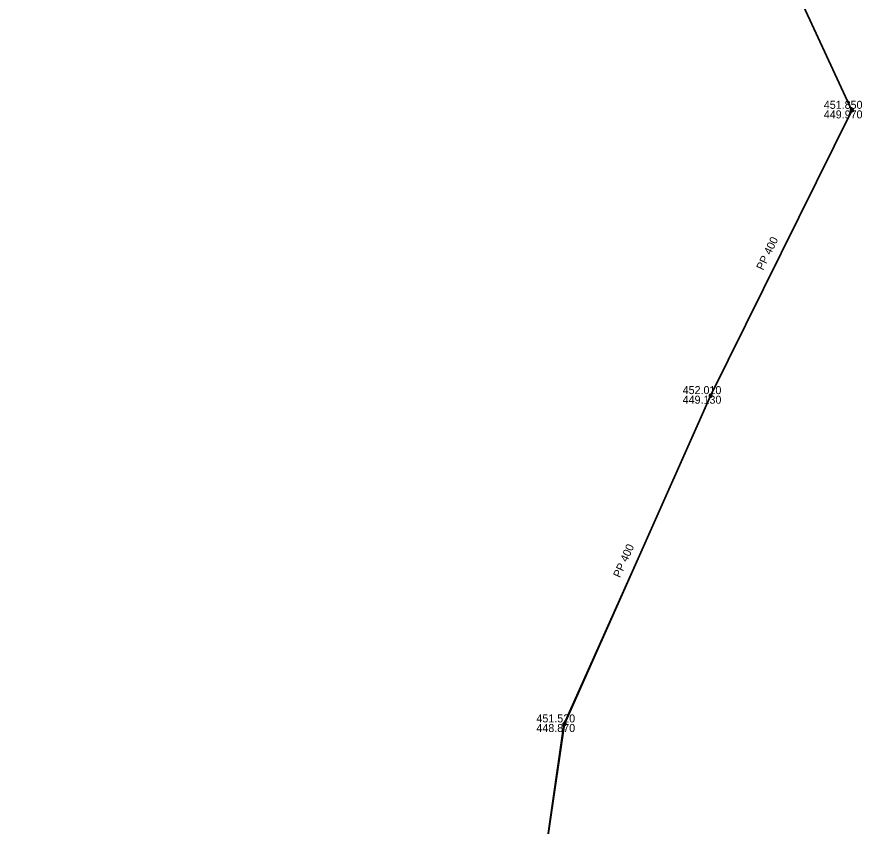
# Model space of a CAD drawing. Extents: x -873619 to -867639, y -1015082 to -1012326.
# Drawn here: x -873191.6 to -873075.5, y -1013871.2 to -1013760 of the extents above; entities that cross this region are included whole.
import ezdxf

# ---------------------------------------------------------------- set-up
doc = ezdxf.new("R2010")
doc.units = 0
doc.header["$LTSCALE"] = 0.44
for name, color, linetype, lineweight in [('1', 7, 'Continuous', 13), ('21', 7, 'Continuous', 35), ('3', 7, 'Continuous', 25), ('32', 7, 'Continuous', 13)]:
    doc.layers.add(name, color=color, linetype=linetype, lineweight=lineweight)

msp = doc.modelspace()

# ---------------------------------------------------------------- linework, layer by layer
at = {"layer": '21'}
for p, q in [((-873099.19, -1013724.68), (-873076.92, -1013772.84)), ((-873076.92, -1013772.84), (-873096.31, -1013812.05)), ((-873096.31, -1013812.05), (-873116.4, -1013857.17)), ((-873116.4, -1013857.17), (-873123.67, -1013906.71))]:
    msp.add_line(p, q, dxfattribs=at)
at = {"layer": '3'}
msp.add_lwpolyline([(-873209.421, -1014292.661), (-873208.998, -1014240.45), (-873211.448, -1014197.31), (-873215.58, -1014166.03), (-873205.44, -1014160.07), (-873195.92, -1014151.84), (-873190.998, -1014149.15), (-873189.02, -1014105.45), (-873184.64, -1014067), (-873178.998, -1014022.35), (-873173.208, -1014002.85), (-873150.578, -1013958.19), (-873123.56, -1013906.71), (-873116.49, -1013857.17), (-873096.298, -1013812.05), (-873076.908, -1013772.84), (-873099.08, -1013724.68), (-873112.568, -1013694.19), (-873154.458, -1013666.63), (-873180.788, -1013644.59), (-873224.641, -1013607.538), (-873251.958, -1013559.37), (-873281.448, -1013506.61), (-873307.717, -1013457.772)], dxfattribs=at)
at = {"layer": '32'}
for points in [[(-873076.679, -1013772.84), (-873076.685, -1013772.788), (-873076.702, -1013772.738), (-873076.731, -1013772.694), (-873076.768, -1013772.657), (-873076.813, -1013772.63), (-873076.863, -1013772.613), (-873076.916, -1013772.609), (-873076.968, -1013772.616), (-873077.017, -1013772.635), (-873077.06, -1013772.664), (-873077.096, -1013772.703), (-873077.122, -1013772.748), (-873077.138, -1013772.799), (-873077.141, -1013772.851), (-873077.133, -1013772.903), (-873077.113, -1013772.952), (-873077.082, -1013772.995), (-873077.043, -1013773.029), (-873076.997, -1013773.055), (-873076.946, -1013773.069), (-873076.893, -1013773.071), (-873076.842, -1013773.061), (-873076.794, -1013773.04), (-873076.751, -1013773.009), (-873076.717, -1013772.968), (-873076.693, -1013772.922), (-873076.681, -1013772.871)], [(-873076.709, -1013772.84), (-873076.715, -1013772.791), (-873076.732, -1013772.745), (-873076.76, -1013772.705), (-873076.797, -1013772.673), (-873076.841, -1013772.651), (-873076.889, -1013772.64), (-873076.938, -1013772.64), (-873076.985, -1013772.653), (-873077.028, -1013772.677), (-873077.064, -1013772.71), (-873077.091, -1013772.751), (-873077.107, -1013772.798), (-873077.111, -1013772.847), (-873077.104, -1013772.895), (-873077.085, -1013772.94), (-873077.055, -1013772.98), (-873077.017, -1013773.011), (-873076.973, -1013773.031), (-873076.925, -1013773.041), (-873076.876, -1013773.039), (-873076.829, -1013773.024), (-873076.786, -1013772.999), (-873076.752, -1013772.965), (-873076.726, -1013772.923), (-873076.712, -1013772.876)], [(-873076.739, -1013772.84), (-873076.745, -1013772.795), (-873076.762, -1013772.753), (-873076.79, -1013772.718), (-873076.826, -1013772.691), (-873076.868, -1013772.674), (-873076.913, -1013772.669), (-873076.958, -1013772.675), (-873076.999, -1013772.694), (-873077.034, -1013772.722), (-873077.061, -1013772.759), (-873077.077, -1013772.801), (-873077.081, -1013772.846), (-873077.074, -1013772.891), (-873077.055, -1013772.932), (-873077.026, -1013772.966), (-873076.989, -1013772.992), (-873076.946, -1013773.008), (-873076.901, -1013773.011), (-873076.856, -1013773.003), (-873076.816, -1013772.983), (-873076.782, -1013772.954), (-873076.756, -1013772.916), (-873076.742, -1013772.873)], [(-873076.769, -1013772.84), (-873076.774, -1013772.799), (-873076.792, -1013772.762), (-873076.819, -1013772.731), (-873076.854, -1013772.71), (-873076.894, -1013772.699), (-873076.935, -1013772.701), (-873076.974, -1013772.714), (-873077.008, -1013772.738), (-873077.033, -1013772.77), (-873077.048, -1013772.808), (-873077.051, -1013772.849), (-873077.043, -1013772.889), (-873077.023, -1013772.925), (-873076.994, -1013772.954), (-873076.957, -1013772.973), (-873076.917, -1013772.981), (-873076.876, -1013772.977), (-873076.838, -1013772.962), (-873076.806, -1013772.936), (-873076.783, -1013772.902), (-873076.77, -1013772.863)], [(-873076.799, -1013772.84), (-873076.804, -1013772.804), (-873076.822, -1013772.772), (-873076.848, -1013772.747), (-873076.882, -1013772.732), (-873076.918, -1013772.729), (-873076.953, -1013772.737), (-873076.984, -1013772.757), (-873077.007, -1013772.785), (-873077.02, -1013772.819), (-873077.02, -1013772.856), (-873077.009, -1013772.891), (-873076.988, -1013772.92), (-873076.958, -1013772.941), (-873076.923, -1013772.951), (-873076.886, -1013772.949), (-873076.852, -1013772.935), (-873076.825, -1013772.912), (-873076.806, -1013772.88), (-873076.799, -1013772.845)], [(-873076.829, -1013772.84), (-873076.834, -1013772.809), (-873076.851, -1013772.783), (-873076.877, -1013772.766), (-873076.907, -1013772.759), (-873076.938, -1013772.763), (-873076.965, -1013772.78), (-873076.983, -1013772.804), (-873076.991, -1013772.835), (-873076.987, -1013772.865), (-873076.972, -1013772.893), (-873076.948, -1013772.912), (-873076.918, -1013772.921), (-873076.887, -1013772.918), (-873076.859, -1013772.904), (-873076.839, -1013772.88), (-873076.829, -1013772.851)], [(-873076.859, -1013772.84), (-873076.864, -1013772.816), (-873076.881, -1013772.798), (-873076.904, -1013772.789), (-873076.928, -1013772.792), (-873076.949, -1013772.806), (-873076.96, -1013772.828), (-873076.96, -1013772.853), (-873076.948, -1013772.874), (-873076.928, -1013772.888), (-873076.903, -1013772.891), (-873076.88, -1013772.882), (-873076.864, -1013772.864)], [(-873076.889, -1013772.84), (-873076.894, -1013772.825), (-873076.909, -1013772.819), (-873076.924, -1013772.823), (-873076.931, -1013772.837), (-873076.927, -1013772.852), (-873076.914, -1013772.861), (-873076.899, -1013772.858), (-873076.889, -1013772.846)], [(-873096.069, -1013812.05), (-873096.075, -1013811.998), (-873096.092, -1013811.948), (-873096.121, -1013811.904), (-873096.158, -1013811.867), (-873096.203, -1013811.84), (-873096.253, -1013811.823), (-873096.306, -1013811.819), (-873096.358, -1013811.826), (-873096.407, -1013811.845), (-873096.45, -1013811.874), (-873096.486, -1013811.913), (-873096.512, -1013811.958), (-873096.528, -1013812.009), (-873096.531, -1013812.061), (-873096.523, -1013812.113), (-873096.503, -1013812.162), (-873096.472, -1013812.205), (-873096.433, -1013812.239), (-873096.387, -1013812.265), (-873096.336, -1013812.279), (-873096.283, -1013812.281), (-873096.232, -1013812.271), (-873096.184, -1013812.25), (-873096.141, -1013812.219), (-873096.107, -1013812.178), (-873096.083, -1013812.132), (-873096.071, -1013812.081)], [(-873096.099, -1013812.05), (-873096.105, -1013812.001), (-873096.122, -1013811.955), (-873096.15, -1013811.915), (-873096.187, -1013811.883), (-873096.231, -1013811.861), (-873096.279, -1013811.85), (-873096.328, -1013811.85), (-873096.375, -1013811.863), (-873096.418, -1013811.887), (-873096.454, -1013811.92), (-873096.481, -1013811.961), (-873096.497, -1013812.008), (-873096.501, -1013812.057), (-873096.494, -1013812.105), (-873096.475, -1013812.15), (-873096.445, -1013812.19), (-873096.407, -1013812.221), (-873096.363, -1013812.241), (-873096.315, -1013812.251), (-873096.266, -1013812.249), (-873096.219, -1013812.234), (-873096.176, -1013812.209), (-873096.142, -1013812.175), (-873096.116, -1013812.133), (-873096.102, -1013812.086)], [(-873096.129, -1013812.05), (-873096.135, -1013812.005), (-873096.152, -1013811.963), (-873096.18, -1013811.928), (-873096.216, -1013811.901), (-873096.258, -1013811.884), (-873096.303, -1013811.879), (-873096.348, -1013811.885), (-873096.389, -1013811.904), (-873096.424, -1013811.932), (-873096.451, -1013811.969), (-873096.467, -1013812.011), (-873096.471, -1013812.056), (-873096.464, -1013812.101), (-873096.445, -1013812.142), (-873096.416, -1013812.176), (-873096.379, -1013812.202), (-873096.336, -1013812.218), (-873096.291, -1013812.221), (-873096.246, -1013812.213), (-873096.206, -1013812.193), (-873096.172, -1013812.164), (-873096.146, -1013812.126), (-873096.132, -1013812.083)], [(-873096.159, -1013812.05), (-873096.164, -1013812.009), (-873096.182, -1013811.972), (-873096.209, -1013811.941), (-873096.244, -1013811.92), (-873096.284, -1013811.909), (-873096.325, -1013811.911), (-873096.364, -1013811.924), (-873096.398, -1013811.948), (-873096.423, -1013811.98), (-873096.438, -1013812.018), (-873096.441, -1013812.059), (-873096.433, -1013812.099), (-873096.413, -1013812.135), (-873096.384, -1013812.164), (-873096.347, -1013812.183), (-873096.307, -1013812.191), (-873096.266, -1013812.187), (-873096.228, -1013812.172), (-873096.196, -1013812.146), (-873096.173, -1013812.112), (-873096.16, -1013812.073)], [(-873096.189, -1013812.05), (-873096.194, -1013812.014), (-873096.212, -1013811.982), (-873096.238, -1013811.957), (-873096.272, -1013811.942), (-873096.308, -1013811.939), (-873096.343, -1013811.947), (-873096.374, -1013811.967), (-873096.397, -1013811.995), (-873096.41, -1013812.029), (-873096.41, -1013812.066), (-873096.399, -1013812.101), (-873096.378, -1013812.13), (-873096.348, -1013812.151), (-873096.313, -1013812.161), (-873096.276, -1013812.159), (-873096.242, -1013812.145), (-873096.215, -1013812.122), (-873096.196, -1013812.09), (-873096.189, -1013812.055)], [(-873096.219, -1013812.05), (-873096.224, -1013812.019), (-873096.241, -1013811.993), (-873096.267, -1013811.976), (-873096.297, -1013811.969), (-873096.328, -1013811.973), (-873096.355, -1013811.99), (-873096.373, -1013812.014), (-873096.381, -1013812.045), (-873096.377, -1013812.075), (-873096.362, -1013812.103), (-873096.338, -1013812.122), (-873096.308, -1013812.131), (-873096.277, -1013812.128), (-873096.249, -1013812.114), (-873096.229, -1013812.09), (-873096.219, -1013812.061)], [(-873096.249, -1013812.05), (-873096.254, -1013812.026), (-873096.271, -1013812.008), (-873096.294, -1013811.999), (-873096.318, -1013812.002), (-873096.339, -1013812.016), (-873096.35, -1013812.038), (-873096.35, -1013812.063), (-873096.338, -1013812.084), (-873096.318, -1013812.098), (-873096.293, -1013812.101), (-873096.27, -1013812.092), (-873096.254, -1013812.074)], [(-873096.279, -1013812.05), (-873096.284, -1013812.035), (-873096.299, -1013812.029), (-873096.314, -1013812.033), (-873096.321, -1013812.047), (-873096.317, -1013812.062), (-873096.304, -1013812.071), (-873096.289, -1013812.068), (-873096.279, -1013812.056)], [(-873116.159, -1013857.17), (-873116.165, -1013857.118), (-873116.182, -1013857.068), (-873116.211, -1013857.024), (-873116.248, -1013856.987), (-873116.293, -1013856.96), (-873116.343, -1013856.943), (-873116.396, -1013856.939), (-873116.448, -1013856.946), (-873116.497, -1013856.965), (-873116.54, -1013856.994), (-873116.576, -1013857.033), (-873116.602, -1013857.078), (-873116.618, -1013857.129), (-873116.621, -1013857.181), (-873116.613, -1013857.233), (-873116.593, -1013857.282), (-873116.562, -1013857.325), (-873116.523, -1013857.359), (-873116.477, -1013857.385), (-873116.426, -1013857.399), (-873116.373, -1013857.401), (-873116.322, -1013857.391), (-873116.274, -1013857.37), (-873116.231, -1013857.339), (-873116.197, -1013857.298), (-873116.173, -1013857.252), (-873116.161, -1013857.201)], [(-873116.189, -1013857.17), (-873116.195, -1013857.121), (-873116.212, -1013857.075), (-873116.24, -1013857.035), (-873116.277, -1013857.003), (-873116.321, -1013856.981), (-873116.369, -1013856.97), (-873116.418, -1013856.97), (-873116.465, -1013856.983), (-873116.508, -1013857.007), (-873116.544, -1013857.04), (-873116.571, -1013857.081), (-873116.587, -1013857.128), (-873116.591, -1013857.177), (-873116.584, -1013857.225), (-873116.565, -1013857.27), (-873116.535, -1013857.31), (-873116.497, -1013857.341), (-873116.453, -1013857.361), (-873116.405, -1013857.371), (-873116.356, -1013857.369), (-873116.309, -1013857.354), (-873116.266, -1013857.329), (-873116.232, -1013857.295), (-873116.206, -1013857.253), (-873116.192, -1013857.206)], [(-873116.219, -1013857.17), (-873116.225, -1013857.125), (-873116.242, -1013857.083), (-873116.27, -1013857.048), (-873116.306, -1013857.021), (-873116.348, -1013857.004), (-873116.393, -1013856.999), (-873116.438, -1013857.005), (-873116.479, -1013857.024), (-873116.514, -1013857.052), (-873116.541, -1013857.089), (-873116.557, -1013857.131), (-873116.561, -1013857.176), (-873116.554, -1013857.221), (-873116.535, -1013857.262), (-873116.506, -1013857.296), (-873116.469, -1013857.322), (-873116.426, -1013857.338), (-873116.381, -1013857.341), (-873116.336, -1013857.333), (-873116.296, -1013857.313), (-873116.262, -1013857.284), (-873116.236, -1013857.246), (-873116.222, -1013857.203)], [(-873116.249, -1013857.17), (-873116.254, -1013857.129), (-873116.272, -1013857.092), (-873116.299, -1013857.061), (-873116.334, -1013857.04), (-873116.374, -1013857.029), (-873116.415, -1013857.031), (-873116.454, -1013857.044), (-873116.488, -1013857.068), (-873116.513, -1013857.1), (-873116.528, -1013857.138), (-873116.531, -1013857.179), (-873116.523, -1013857.219), (-873116.503, -1013857.255), (-873116.474, -1013857.284), (-873116.437, -1013857.303), (-873116.397, -1013857.311), (-873116.356, -1013857.307), (-873116.318, -1013857.292), (-873116.286, -1013857.266), (-873116.263, -1013857.232), (-873116.25, -1013857.193)], [(-873116.279, -1013857.17), (-873116.284, -1013857.134), (-873116.302, -1013857.102), (-873116.328, -1013857.077), (-873116.362, -1013857.062), (-873116.398, -1013857.059), (-873116.433, -1013857.067), (-873116.464, -1013857.087), (-873116.487, -1013857.115), (-873116.5, -1013857.149), (-873116.5, -1013857.186), (-873116.489, -1013857.221), (-873116.468, -1013857.25), (-873116.438, -1013857.271), (-873116.403, -1013857.281), (-873116.366, -1013857.279), (-873116.332, -1013857.265), (-873116.305, -1013857.242), (-873116.286, -1013857.21), (-873116.279, -1013857.175)], [(-873116.309, -1013857.17), (-873116.314, -1013857.139), (-873116.331, -1013857.113), (-873116.357, -1013857.096), (-873116.387, -1013857.089), (-873116.418, -1013857.093), (-873116.445, -1013857.11), (-873116.463, -1013857.134), (-873116.471, -1013857.165), (-873116.467, -1013857.195), (-873116.452, -1013857.223), (-873116.428, -1013857.242), (-873116.398, -1013857.251), (-873116.367, -1013857.248), (-873116.339, -1013857.234), (-873116.319, -1013857.21), (-873116.309, -1013857.181)], [(-873116.339, -1013857.17), (-873116.344, -1013857.146), (-873116.361, -1013857.128), (-873116.384, -1013857.119), (-873116.408, -1013857.122), (-873116.429, -1013857.136), (-873116.44, -1013857.158), (-873116.44, -1013857.183), (-873116.428, -1013857.204), (-873116.408, -1013857.218), (-873116.383, -1013857.221), (-873116.36, -1013857.212), (-873116.344, -1013857.194)], [(-873116.369, -1013857.17), (-873116.374, -1013857.155), (-873116.389, -1013857.149), (-873116.404, -1013857.153), (-873116.411, -1013857.167), (-873116.407, -1013857.182), (-873116.394, -1013857.191), (-873116.379, -1013857.188), (-873116.369, -1013857.176)]]:
    msp.add_lwpolyline(points, close=True, dxfattribs=at)

# ---------------------------------------------------------------- texts
at = {"layer": '1'}
for s, p in [('451.850 ', (-873080.76, -1013772.62)), ('449.970 ', (-873080.76, -1013773.94)), ('452.010 ', (-873100.15, -1013811.83)), ('449.130 ', (-873100.15, -1013813.15)), ('451.520 ', (-873120.24, -1013856.95)), ('448.870 ', (-873120.24, -1013858.27))]:
    msp.add_text(s, height=1.1, dxfattribs=at).set_placement(p)
for rotation, p in [(64, (-873089.107, -1013794.892)), (66, (-873108.747, -1013837.156))]:
    msp.add_text('PP 400', height=1.1, rotation=rotation, dxfattribs=at).set_placement(p)

doc.saveas('drawing.dxf')
